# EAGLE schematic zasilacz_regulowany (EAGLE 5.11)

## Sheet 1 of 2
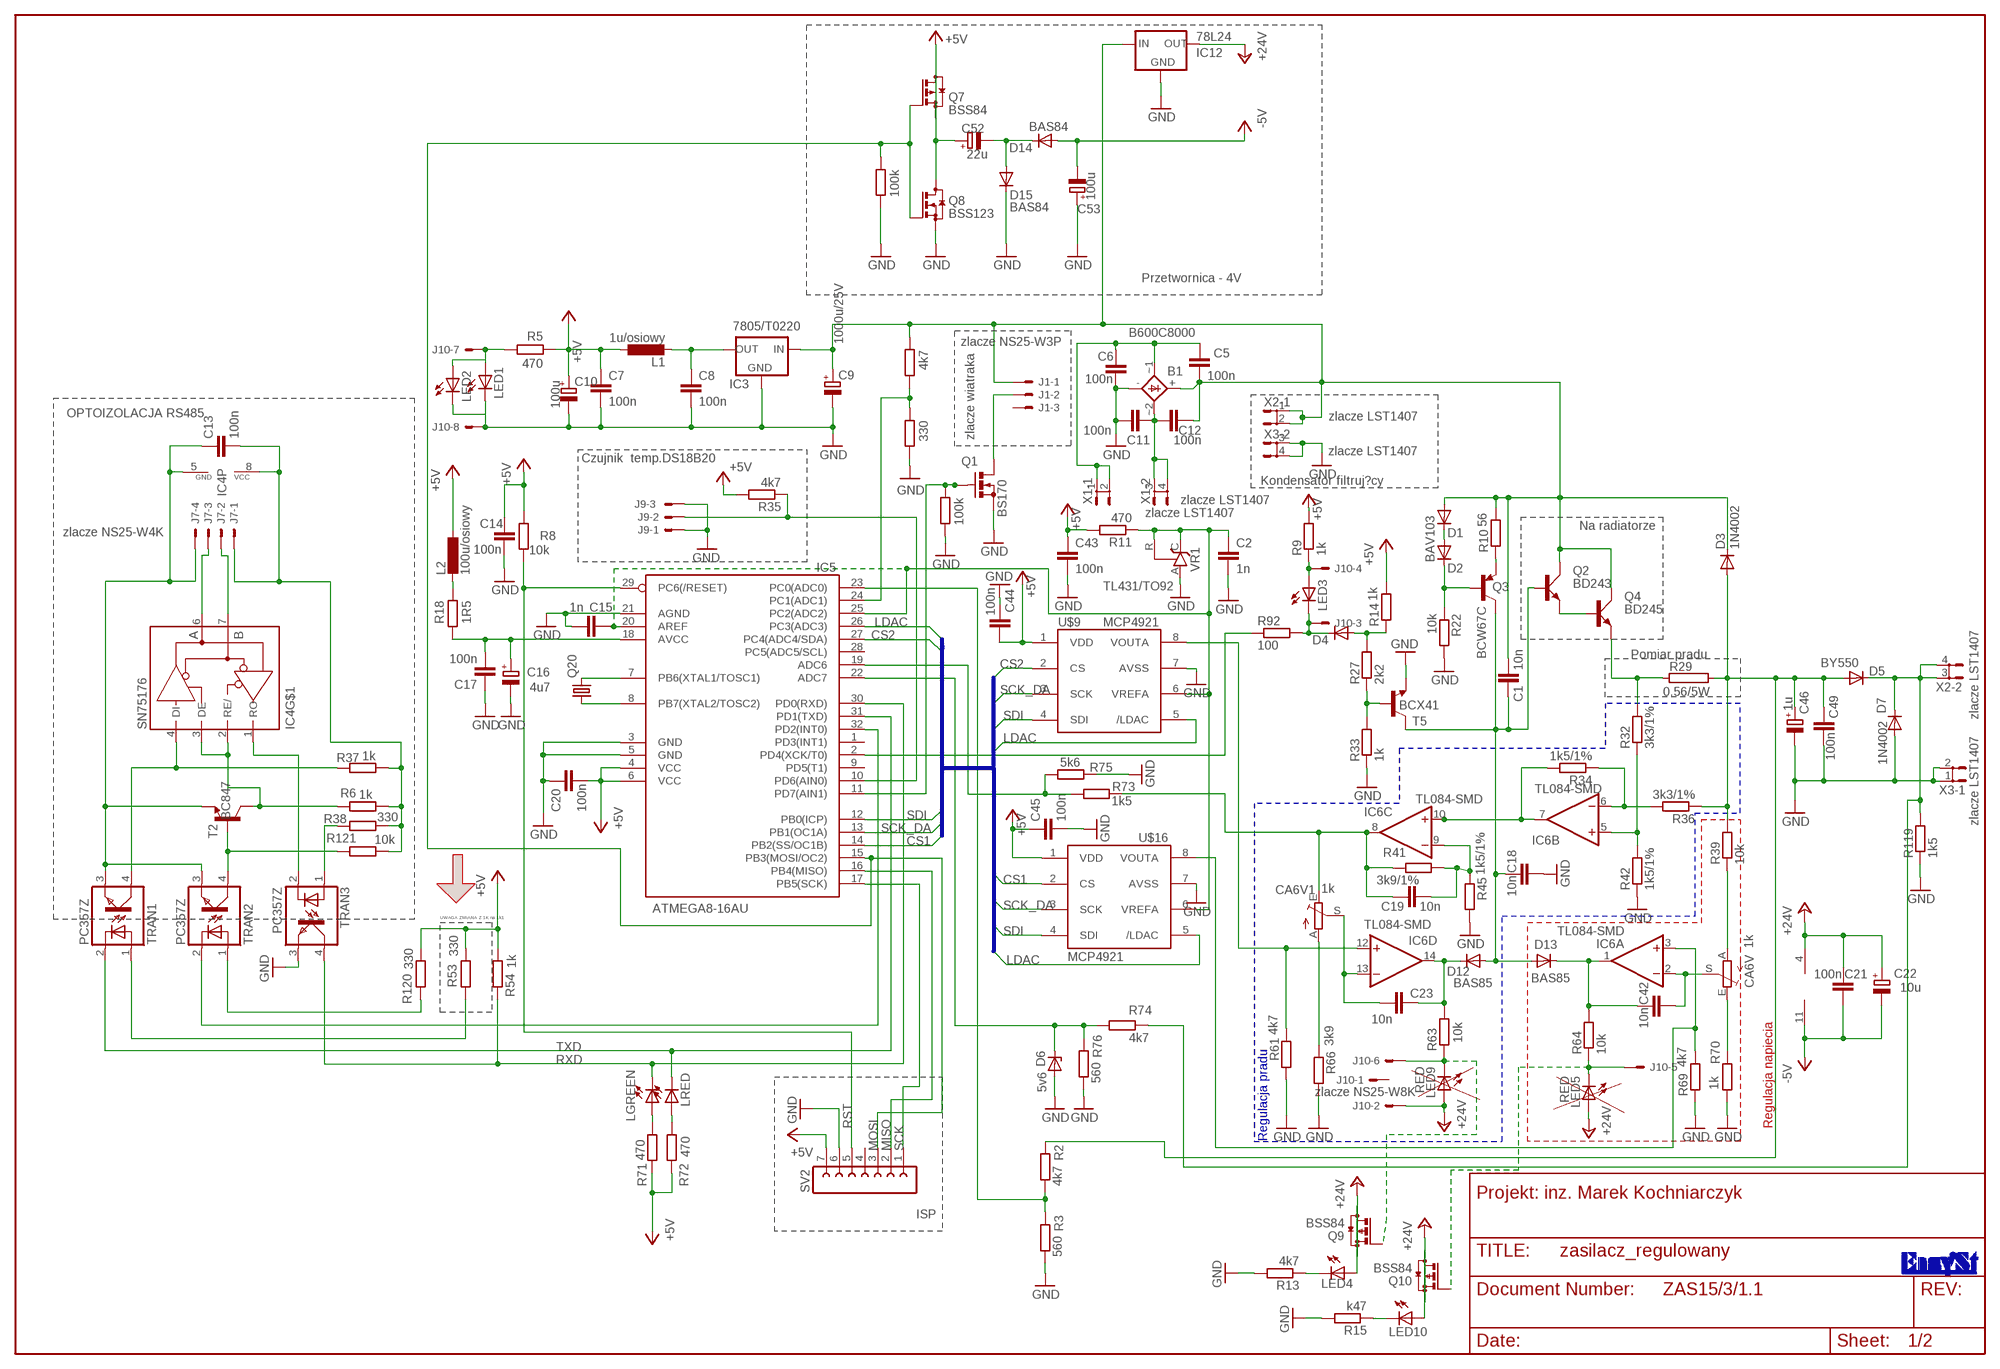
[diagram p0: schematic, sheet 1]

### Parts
B1  B600C8000  2KBB_R2  [2KBB_R2]
C1  10n  C-EUC0805  [C0805]
C2  1n  C-EUC0805  [C0805]
C5  100n  C-EUC0805  [C0805]
C6  100n  C-EUC0805  [C0805]
C7  100n  C-EUC0805  [C0805]
C8  100n  C-EUC0805  [C0805]
C9  1000u/25V  CPOL-EUTT5D11  [TT5D11]
C10  100u  CPOL-EUTT2D5  [TT2D5]
C11  100n  C-EUC0805  [C0805]
C12  100n  C-EUC0805  [C0805]
C13  100n  C-EUC0805  [C0805]
C14  100n  C-EUC0805  [C0805]
C15  1n  C-EUC0805  [C0805]
C16  4u7  CPOL-EUTT2D5  [TT2D5]
C17  100n  C-EUC0805  [C0805]
C18  10n  C-EUC0805  [C0805]
C19  10n  C-EUC0805  [C0805]
C20  100n  C-EUC0805  [C0805]
C21  100n  C-EUC0805  [C0805]
C22  10u  CPOL-EUTT2D5  [TT2D5]
C23  10n  C-EUC0805  [C0805]
C42  10n  C-EUC0805  [C0805]
C43  100n  C-EUC0805  [C0805]
C44  100n  C-EUC0805  [C0805]
C45  100n  C-EUC0805  [C0805]
C46  1u  CPOL-EUTT2D5  [TT2D5]
C49  100n  C-EUC0805  [C0805]
C52  22u  CPOL-EUTT2D5  [TT2D5]
C53  100u  CPOL-EUTT2D6  [TT2D6]
CA6V  1k  TRIM_EU-CA6H  [CA6H]
CA6V1  1k  TRIM_EU-CA6H  [CA6H]
D1  BAV103  DIODE-MINIMELF  [MINIMELF]
D2  BAV103  DIODE-MINIMELF  [MINIMELF]
D3  1N4002  DIODE-P1-10  [P1-10]
D4  DIODE-MINIMELF  [MINIMELF]
D5  BY550  DIODE-P6-15  [P6-15]
D6  5v6  ZENER-DIODESOT23  [SOT23]
D7  1N4002  DIODE-P1-10  [P1-10]
D12  BAS85  DIODE-MINIMELF  [MINIMELF]
D13  BAS85  DIODE-MINIMELF  [MINIMELF]
D14  BAS85  DIODE-MINIMELF  [MINIMELF]
D15  BAS85  DIODE-MINIMELF  [MINIMELF]
IC3  7805/T0220  78XXS  [78XXS]
IC4  SN75176  MAX481CSA  [SO08]
IC5  ATMEGA8-16AU  MEGA8-AI  [TQFP32-08]
IC6  TL084-SMD  TL084D  [SO14]
IC12  78L24  78LXX  [78LXX]
J1  zlacze NS25-W3P  22-27-2031-03  [6410-03]
J7  zlacze NS25-W4K  22-05-7048-04  [7395-04]
J9  zlacze NS25-W3P  22-27-2031-03  [6410-03]
J10  zlacze NS25-W8K  22-05-7088-08  [7395-08]
L1  1u/osiowy  L-EU0207/12  [0207/12]
L2  100u/osiowy  L-EU0207/10  [0207/10]
LED1  LED3MM  [LED3MM]
LED2  LED3MM  [LED3MM]
LED3  LED3MM  [LED3MM]
LED4  RED  LED3MM  [LED3MM]
LED5  RED  LED3MM  [LED3MM]
LED9  RED  LED3MM  [LED3MM]
LED10  RED  LED3MM  [LED3MM]
LGREEN  1206  LEDSMT1206  [1206]
LRED  1206  LEDSMT1206  [1206]
Q1  BS170  [SOT54E]
Q2  BD243  TIP41C  [TO220AV]
Q3  BCW67C  BCX71SMD  [SOT23]
Q4  BD245  TIP3055  [TOP3AV]
Q7  BSS84  [SOT23]
Q8  BSS123  [SOT23]
Q9  BSS84  [SOT23]
Q10  BSS84  [SOT23]
Q20  CRYSTALHC49S  [HC49/S]
R1  100k  R-EU_R0805  [R0805]
R2  4k7  R-EU_R0805  [R0805]
R3  560  R-EU_R0805  [R0805]
R4  4k7  R-EU_R0805  [R0805]
R5  470  R-EU_R0805  [R0805]
R6  1k  R-EU_R0805  [R0805]
R7  100k  R-EU_M0805  [M0805]
R8  10k  R-EU_R0805  [R0805]
R9  1k  R-EU_R0805  [R0805]
R10  56  R-EU_0207/10  [0207/10]
R11  470  R-EU_R0805  [R0805]
R12  330  R-EU_R0805  [R0805]
R13  4k7  R-EU_R0805  [R0805]
R14  1k  R-EU_R0805  [R0805]
R15  k47  R-EU_R0805  [R0805]
R18  1R5  R-EU_R0805  [R0805]
R22  10k  R-EU_R0805  [R0805]
R27  2k2  R-EU_R0805  [R0805]
R29  0.56/5W  RKH208-8  [KH208-8]
R32  3k3/1%  R-EU_R0805  [R0805]
R33  1k  R-EU_R0805  [R0805]
R34  1k5/1%  R-EU_R0805  [R0805]
R35  4k7  R-EU_R0805  [R0805]
R36  3k3/1%  R-EU_R0805  [R0805]
R37  1k  R-EU_R0805  [R0805]
R38  330  R-EU_M0805  [M0805]
R39  10k  R-EU_R0805  [R0805]
R41  3k9/1%  R-EU_R0805  [R0805]
R42  1k5/1%  R-EU_R0805  [R0805]
R45  1k5/1%  R-EU_R0805  [R0805]
R53  330  R-EU_R0805  [R0805]
R54  1k  R-EU_R0805  [R0805]
R61  4k7  R-EU_R0805  [R0805]
R63  10k  R-EU_R0805  [R0805]
R64  10k  R-EU_R0805  [R0805]
R66  3k9  R-EU_R0805  [R0805]
R69  4k7  R-EU_R0805  [R0805]
R70  1k  R-EU_R0805  [R0805]
R71  470  R-EU_R0805  [R0805]
R72  470  R-EU_R0805  [R0805]
R73  1k5  R-EU_R0805  [R0805]
R74  4k7  R-EU_R0805  [R0805]
R75  5k6  R-EU_R0805  [R0805]
R76  560  R-EU_R0805  [R0805]
R92  100  R-EU_R0805  [R0805]
R119  1k5  R-EU_0207/7  [0207/7]
R120  330  R-EU_R0805  [R0805]
R121  10k  R-EU_R0805  [R0805]
SV2  FE07-1  [FE07]
T2  BC847  BCX70SMD  [SOT23]
T5  BCX41  BCX70SMD  [SOT23]
TRAN1  PC357Z  [MFP4]
TRAN2  PC357Z  [MFP4]
TRAN3  PC357Z  [MFP4]
U$9  MCP4921  [SO-08]
U$16  MCP4921  [SO-08]
VR1  TL431/TO92  TL431CLP  [TO92-CLP]
X1  zlacze LST1407  SH5-2  [SH5-2]
X2  zlacze LST1407  SH5-2  [SH5-2]
X3  zlacze LST1407  SH5-2  [SH5-2]

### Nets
+5V: C7.1 C10.+ C14.1 C20.2 C43.1 C44.2 C45.1 IC5.4(VCC) IC5.6(VCC) L1.1 L2.1 Q7.2(S) R5.1 R8.2 R9.2 R11.2 R14.2 R35.2 R53.1 R54.1 R71.1 R72.1 R120.1 SV2.7 U$9.1(VDD) U$16.1(VDD) ; also sheet 2
+24V: C21.1 C22.+ IC6.4(P:V+) IC12.OUT J10.2 LED5.A LED9.A Q9.2(S) Q10.2(S)
-5V: C21.2 C22.- C53.- D14.A IC6.11(P:V-)
A: IC4.6(A) J7.3
ADC6: IC5.19(ADC6) R73.2 R75.2
ADC7: D6.3(C) IC5.22(ADC7) R74.1 R76.2
AVCC: C16.+ C17.2 IC5.18(AVCC) R18.2
B: IC4.7(B) J7.2
CS1: IC5.14(PB2(SS/OC1B)) U$16.2(CS)
CS2: IC5.27(PC4(ADC4/SDA)) U$9.2(CS)
GND: B1.- C2.2 C6.2 C7.2 C8.2 C9.- C10.- C11.1 C14.2 C15.1 C16.- C17.1 C18.2 C20.1 C43.2 C44.1 C45.2 C46.- C49.1 C53.+ D6.1(A) D7.A D15.C IC3.GND IC5.3(GND) IC5.5(GND) IC5.21(AGND) IC12.GND J9.1 J9.3 J10.8 LED1.K(C) LED2.K(C) Q1.S Q8.2(S) R1.2 R3.1 R7.2 R12.2 R13.2 R15.2 R22.2 R33.1 R42.1 R45.2 R61.1 R66.2 R69.1 R70.1 R75.1 R76.1 R119.1 SV2.6 T5.2(E) TRAN3.3(EMIT) U$9.7(AVSS) U$16.7(AVSS) VR1.A X3.1 X3.2 X3.3 X3.4
GND_RS485: C13.1 IC4.5(P:GND) J7.4 T2.2(E) TRAN1.3(EMIT) TRAN2.3(EMIT)
IOUT: IC6.12(D:+IN) R61.2 U$9.8(VOUTA)
LDAC: IC5.26(PC3(ADC3)) U$9.5(/LDAC) U$16.5(/LDAC)
MISO: IC5.16(PB4(MISO)) SV2.2
MOSI: IC5.15(PB3(MOSI/OC2)) Q7.1(G) Q8.1(G) R1.1 SV2.3
N$1: CA6V.A R39.1
N$2: IC6.6(B:-IN) R34.1 R36.2
N$3: C42.2 CA6V.S IC6.2(A:-IN)
N$4: IC6.5(B:+IN) R32.1 R42.2
N$5: IC6.7(B:OUT) IC6.10(C:+IN) R34.2
N$6: C23.1 CA6V1.S IC6.13(D:-IN)
N$7: C19.2 IC6.9(C:-IN) R41.2 R45.1
N$8: C19.1 CA6V1.E IC6.8(C:OUT) R41.1 R73.1
N$10: C1.1 C18.1 D12.A D13.A Q2.B Q3.3(C) T5.3(C)
N$11: R120.2 TRAN2.1(A)
N$12: IC5.32(PD2(INT0)) TRAN2.2(C)
N$14: CA6V.E R70.2
N$16: C23.2 D12.C IC6.14(D:OUT) R63.2
N$17: CA6V1.A R66.1
N$19: Q4.E R29.1 R32.2
N$22: D4.A R14.1 R27.2
N$23: D1.C D2.A
N$25: R27.1 R33.2 T5.1(B)
N$28: Q2.E Q4.B
N$31: LED4.A Q9.3(D)
N$33: C52.+ Q7.3(D) Q8.3(D)
N$34: IC4.4(DI) R37.2 TRAN1.4(COL)
N$35: IC5.10(PD6(AIN0)) J9.2 R35.1
N$36: D2.C Q3.1(B) R22.1
N$37: J10.6 LED9.K(C) Q9.1(G) R63.1
N$38: J10.5 LED5.K(C) Q10.1(G) R64.1
N$39: IC5.23(PC0(ADC0)) R2.1 R3.2
N$40: C46.+ C49.2 D3.A D5.A R2.2 R29.2 R36.1 R39.2
N$42: C52.- D14.C D15.A
N$43: L2.2 R18.1
N$44: R53.2 TRAN1.1(A)
N$45: IC4.1(RO) TRAN3.2(C)
N$47: IC5.7(PB6(XTAL1/TOSC1)) Q20.2
N$54: R38.2 TRAN3.1(A)
N$55: R121.2 T2.1(B) TRAN2.4(COL)
N$56: C8.1 IC3.OUT L1.2
N$57: J10.7 LED1.A LED2.A R5.2
N$59: D5.C D7.C R74.2 R119.2 X2.3 X2.4
N$60: C42.1 D13.C IC6.1(A:OUT) R64.2
N$64: LRED.A R72.2
N$65: IC4.2(RE/) IC4.3(DE) R6.2 T2.3(C)
N$66: LGREEN.A R71.2
N$67: Q3.2(E) R10.1
N$68: B1.~2(AC2) C11.2 C12.1 X1.3 X1.4
N$69: B1.~1(AC1) C5.1 C6.1 X1.1 X1.2
N$100: D4.C J10.3 LED3.K(C) R92.2
N$112: J1.2 Q1.D
N$115: IC5.11(PD7(AIN1)) Q1.G R7.1
N$124: LED4.K(C) R13.1
N$126: LED10.A Q10.3(D)
N$128: LED10.K(C) R15.1
N$130: IC5.8(PB7(XTAL2/TOSC2)) Q20.1
N$142: C2.1 C15.2 IC5.20(AREF) IC5.25(PC2(ADC2)) R11.1 U$9.6(VREFA) U$16.6(VREFA) VR1.C VR1.R
N$144: J10.4 LED3.A R9.1
RST: IC5.29(PC6(/RESET)) R8.1 SV2.5
RXD: IC5.30(PD0(RXD)) LGREEN.C R54.2 TRAN3.4(COL)
SCK: IC5.17(PB5(SCK)) SV2.1
SCK_DA: IC5.13(PB1(OC1A)) U$9.3(SCK) U$16.3(SCK)
SDI: IC5.12(PB0(ICP)) U$9.4(SDI) U$16.4(SDI)
TXD: IC5.31(PD1(TXD)) LRED.C TRAN1.2(C)
V+: B1.+ C1.2 C5.2 C9.+ C12.2 D1.A D3.C IC3.IN IC12.IN J1.1 Q2.C Q4.C R4.1 R10.2 X2.1 X2.2
V_WE: IC5.24(PC1(ADC1)) R4.2 R12.1
VCC_RS485: C13.2 IC4.8(P:VCC) J7.1 R6.1 R37.1 R38.1 R121.1
VOUT: IC6.3(A:+IN) R69.2 U$16.8(VOUTA)
ZAS_ON_OFF: IC5.2(PD4(XCK/T0)) R92.1
Unconnected: IC5.1(PD3(INT1)) IC5.9(PD5(T1)) IC5.28(PC5(ADC5/SCL)) J1.3 J10.1 SV2.4

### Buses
CS1,CS2,SCK_DA,SDI,LDAC

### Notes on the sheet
- BAS84
- BAS84
- Przetwornica - 4V
- OPTOIZOLACJA RS485
- zlacze wiatraka
- Czujnik  temp.DS18B20
- Kondensator filtruj?cy
- Na radiatorze
- BAV103
- Pomiar pradu
- ATMEGA8-16AU
- UWAGA ZMIANA Z 1K na 1k1
- Regulacja napiecia
- Regulacja pradu
- Projekt: inz. Marek Kochniarczyk
- ISP
- D:/logo_ensyst_1bit.bmp
- ZAS15/3/1.1

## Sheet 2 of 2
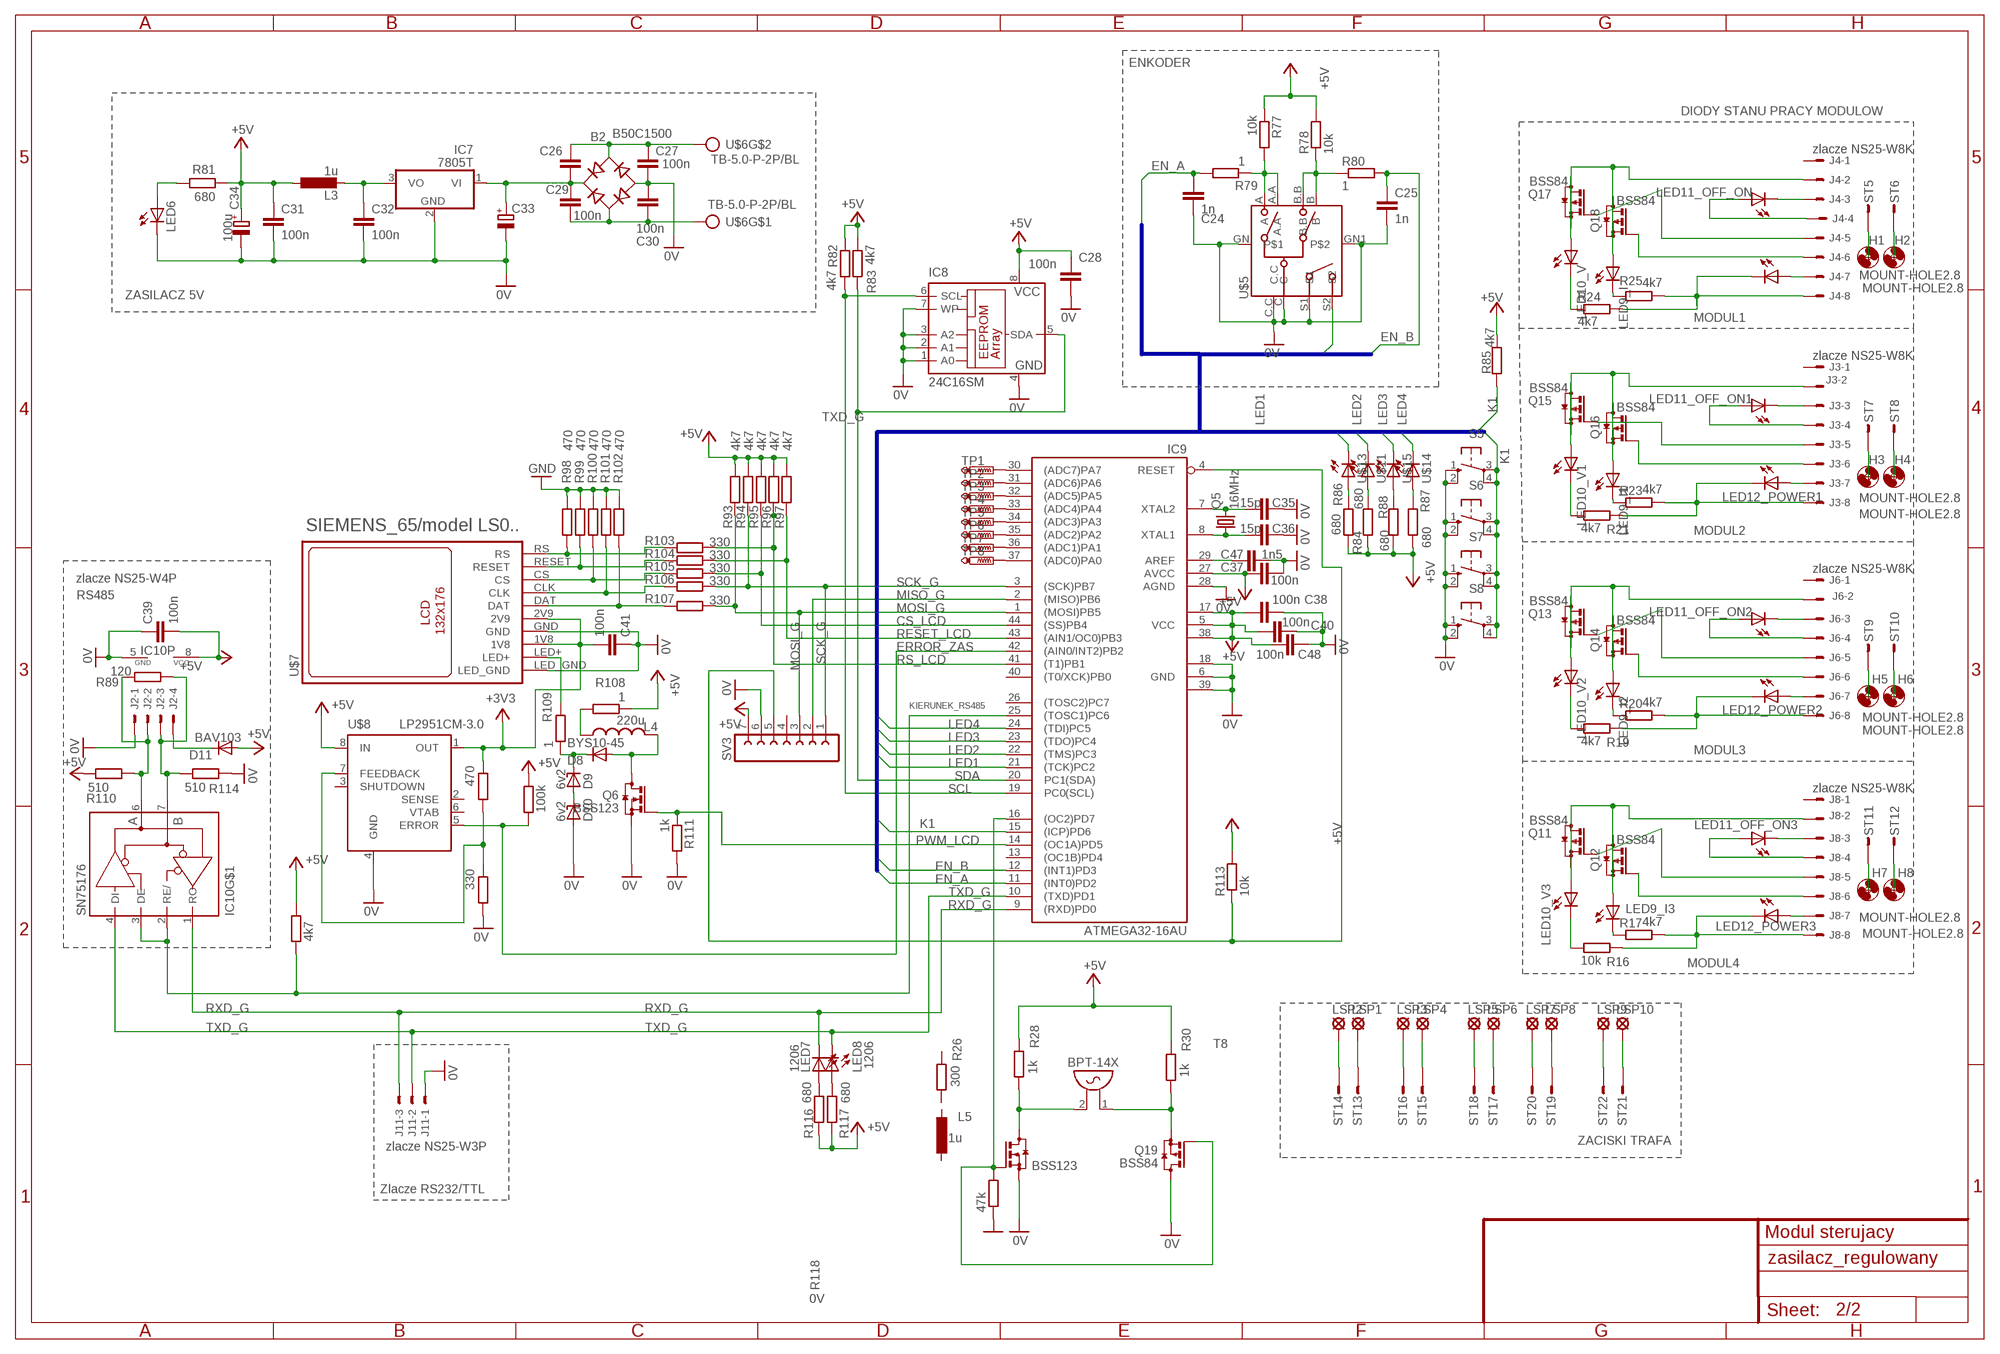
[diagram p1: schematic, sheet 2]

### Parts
B2  B50C1500  RB1A  [RB1A]
BPT-14X  BPT-14X  F/HGP  [F/HGP]
C24  1n  C-EUC0805  [C0805]
C25  1n  C-EUC0805  [C0805]
C26  100n  C-EUC1206  [C1206]
C27  100n  C-EUC1206  [C1206]
C28  100n  C-EUC0805  [C0805]
C29  100n  C-EUC1206  [C1206]
C30  100n  C-EUC1206  [C1206]
C31  100n  C-EUC0805  [C0805]
C32  100n  C-EUC0805  [C0805]
C33  1000u/25V  CPOL-EUTT5D11L  [TT5D11L]
C34  100u  CPOL-EUTT2D5L  [TT2D5L]
C35  15p  C-EUC0805K  [C0805K]
C36  15p  C-EUC0805K  [C0805K]
C37  100n  C-EUC0805K  [C0805K]
C38  100n  C-EUC0805K  [C0805K]
C39  100n  C-EUC0805  [C0805]
C40  100n  C-EUC0805K  [C0805K]
C41  100n  C-EUC0805K  [C0805K]
C47  1n5  C-EUC0805K  [C0805K]
C48  100n  C-EUC0805K  [C0805K]
D8  BYS10-45  BYS10  [SOD106A]
D9  6v2  BZX84CSMD  [TO236]
D10  6v2  BZX84CSMD  [TO236]
D11  BAV103  DIODE-MINIMELF  [MINIMELF]
H1  MOUNT-HOLE2.8  [2,8]
H2  MOUNT-HOLE2.8  [2,8]
H3  MOUNT-HOLE2.8  [2,8]
H4  MOUNT-HOLE2.8  [2,8]
H5  MOUNT-HOLE2.8  [2,8]
H6  MOUNT-HOLE2.8  [2,8]
H7  MOUNT-HOLE2.8  [2,8]
H8  MOUNT-HOLE2.8  [2,8]
IC7  7805T  [TO220H]
IC8  24C16SM  24C64SM  [SO-08M]
IC9  ATMEGA32-16AU  MEGA32-A  [TQFP44]
IC10  SN75176  MAX481CSA  [SO08]
J2  zlacze NS25-W4P  22-27-2041-04  [6410-04]
J3  zlacze NS25-W8K  22-27-2081-08  [6410-08]
J4  zlacze NS25-W8K  22-27-2081-08  [6410-08]
J6  zlacze NS25-W8K  22-27-2081-08  [6410-08]
J8  zlacze NS25-W8K  22-27-2081-08  [6410-08]
J11  zlacze NS25-W3P  22-27-2031-03  [6410-03]
L3  1u  L-EU0207/15  [0207/15@1]
L4  220u  L-US0207/12  [0207/12]
L5  1u  L-EU0207/15  [0207/15@1]
LED6  LED3mm  LED3MM  [LED3MM]
LED7  1206  LEDCHIPLED_1206  [CHIPLED_1206]
LED8  1206  LEDCHIPLED_1206  [CHIPLED_1206]
LED9_I  LED3MM  [LED3MM]
LED9_I1  LED3MM  [LED3MM]
LED9_I2  LED3MM  [LED3MM]
LED9_I3  LED3MM  [LED3MM]
LED10_V  LED3MM  [LED3MM]
LED10_V1  LED3MM  [LED3MM]
LED10_V2  LED3MM  [LED3MM]
LED10_V3  LED3MM  [LED3MM]
LED11_OFF_ON  LED3MM  [LED3MM]
LED11_OFF_ON1  LED3MM  [LED3MM]
LED11_OFF_ON2  LED3MM  [LED3MM]
LED11_OFF_ON3  LED3MM  [LED3MM]
LED12_POWER  LED3MM  [LED3MM]
LED12_POWER1  LED3MM  [LED3MM]
LED12_POWER2  LED3MM  [LED3MM]
LED12_POWER3  LED3MM  [LED3MM]
LSP1  SE14  [SE14]
LSP2  SE14  [SE14]
LSP3  SE14  [SE14]
LSP4  SE14  [SE14]
LSP5  SE14  [SE14]
LSP6  SE14  [SE14]
LSP7  SE14  [SE14]
LSP8  SE14  [SE14]
LSP9  SE14  [SE14]
LSP10  SE14  [SE14]
Q5  16MHz  CRYSTALHC49U70  [HC49U70]
Q6  BSS123  [SOT23]
Q11  BSS84  [SOT23]
Q12  BSS84  [SOT23]
Q13  BSS84  [SOT23]
Q14  BSS84  [SOT23]
Q15  BSS84  [SOT23]
Q16  BSS84  [SOT23]
Q17  BSS84  [SOT23]
Q18  BSS84  [SOT23]
Q19  BSS84  [SOT23]
R16  10k  R-EU_R0805  [R0805]
R17  4k7  R-EU_R0805  [R0805]
R19  4k7  R-EU_R0805  [R0805]
R20  4k7  R-EU_R0805  [R0805]
R21  4k7  R-EU_R0805  [R0805]
R23  4k7  R-EU_R0805  [R0805]
R24  4k7  R-EU_R0805  [R0805]
R25  4k7  R-EU_R0805  [R0805]
R26  300  R-EU_R0805  [R0805]
R28  1k  R-EU_R0805  [R0805]
R30  1k  R-EU_R0805  [R0805]
R77  10k  R-EU_M1206  [M1206]
R78  10k  R-EU_M1206  [M1206]
R79  1  R-EU_M1206  [M1206]
R80  1  R-EU_M1206  [M1206]
R81  680  R-EU_M0805  [M0805]
R82  4k7  R-EU_M0805  [M0805]
R83  4k7  R-EU_M0805  [M0805]
R84  680  R-EU_R0805  [R0805]
R85  4k7  R-EU_R0805  [R0805]
R86  680  R-EU_R0805  [R0805]
R87  680  R-EU_R0805  [R0805]
R88  680  R-EU_R0805  [R0805]
R89  120  R-EU_R0805  [R0805]
R90  470  R-EU_R0805  [R0805]
R91  330  R-EU_R0805  [R0805]
R93  4k7  R-EU_R0805  [R0805]
R94  4k7  R-EU_R0805  [R0805]
R95  4k7  R-EU_R0805  [R0805]
R96  4k7  R-EU_R0805  [R0805]
R97  4k7  R-EU_R0805  [R0805]
R98  470  R-EU_R0805  [R0805]
R99  470  R-EU_R0805  [R0805]
R100  470  R-EU_R0805  [R0805]
R101  470  R-EU_R0805  [R0805]
R102  470  R-EU_R0805  [R0805]
R103  330  R-EU_R0805  [R0805]
R104  330  R-EU_R0805  [R0805]
R105  330  R-EU_R0805  [R0805]
R106  330  R-EU_R0805  [R0805]
R107  330  R-EU_R0805  [R0805]
R108  1  R-EU_R0805  [R0805]
R109  1  R-EU_R0805  [R0805]
R110  510  R-EU_R0805  [R0805]
R111  1k  R-EU_R0805  [R0805]
R112  100k  R-EU_R0805  [R0805]
R113  10k  R-EU_M0805  [M0805]
R114  510  R-EU_R0805  [R0805]
R115  4k7  R-EU_M0805  [M0805]
R116  680  R-EU_M0805  [M0805]
R117  680  R-EU_M0805  [M0805]
R118  47k  R-EU_R0805  [R0805]
S5  10-XX  [B3F-10XX]
S6  10-XX  [B3F-10XX]
S7  10-XX  [B3F-10XX]
S8  10-XX  [B3F-10XX]
ST5  ST2,8  [ST2,8]
ST6  ST2,8  [ST2,8]
ST7  ST2,8  [ST2,8]
ST8  ST2,8  [ST2,8]
ST9  ST2,8  [ST2,8]
ST10  ST2,8  [ST2,8]
ST11  ST2,8  [ST2,8]
ST12  ST2,8  [ST2,8]
ST13  ST2,8  [ST2,8]
ST14  ST2,8  [ST2,8]
ST15  ST2,8  [ST2,8]
ST16  ST2,8  [ST2,8]
ST17  ST2,8  [ST2,8]
ST18  ST2,8  [ST2,8]
ST19  ST2,8  [ST2,8]
ST20  ST2,8  [ST2,8]
ST21  ST2,8  [ST2,8]
ST22  ST2,8  [ST2,8]
SV3  FE07-1  [FE07]
T8  BSS123  [SOT23]
TP1  PTR1B1,27  [B1,27]
TP2  PTR1B1,27  [B1,27]
TP3  PTR1B1,27  [B1,27]
TP4  PTR1B1,27  [B1,27]
TP5  PTR1B1,27  [B1,27]
TP6  PTR1B1,27  [B1,27]
TP7  PTR1B1,27  [B1,27]
TP8  PTR1B1,27  [B1,27]
U$5  ED16112O  [ENKODER_PROSTY]
U$6  TB-5.0-P-2P/BL  AK300/2_MK  [AK300/2_MK]
U$7  SIEMENS_65/model LS0..  SIEMENS_65  [SIEMENS65]
U$8  LP2951CM-3.0  LM2951  [SO08]
U$11  LED3MM  [LED3MM]
U$13  LED3MM  [LED3MM]
U$14  LED3MM  [LED3MM]
U$15  LED3MM  [LED3MM]

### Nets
0V: B2.- C24.2 C25.2 C27.2 C28.2 C30.1 C31.2 C32.2 C33.- C34.- C35.1 C36.1 C37.2 C38.1 C39.1 C40.1 C41.1 C47.2 C48.1 D10.A IC7.2(GND) IC8.1(A0) IC8.2(A1) IC8.3(A2) IC8.4(GND) IC8.7(WP) IC9.6(GND) IC9.18(GND1) IC9.28(AGND) IC9.39(GND2) IC10.5(P:GND) J2.1 J11.1 LED6.K(C) Q6.2(S) Q19.3(D) R91.1 R98.2 R99.2 R100.2 R101.2 R102.2 R111.2 R114.1 R118.1 S5.1(S) S5.2(S1) S6.1(S) S6.2(S1) S7.1(S) S7.2(S1) S8.1(S) S8.2(S1) SV3.6 T8.2(S) U$5.C U$5.C.C U$5.GN U$5.GN1 U$5.S1 U$7.GND U$7.LED_GND U$8.4(GND) ; supply symbol labelled GND
+3V3: C41.2 R90.2 U$7.1V8 U$7.2V9 U$8.1(OUT)
+5V: C28.1 C31.1 C34.+ C37.1 C38.2 C39.2 C40.2 C48.2 D11.A IC8.8(VCC) IC9.5(VCC) IC9.17(VCC1) IC9.27(AVCC) IC9.38(VCC2) IC10.8(P:VCC) L3.1 R28.2 R30.2 R77.1 R78.2 R81.1 R82.1 R83.1 R84.1 R85.1 R86.1 R87.1 R88.1 R93.2 R94.2 R95.2 R96.2 R97.2 R108.1 R110.2 R112.2 R113.2 R115.2 R116.1 R117.1 SV3.7 U$8.8(IN) ; also sheet 1
+_1: ST5.1(ST)
+_2: ST7.1(ST)
+_3: ST9.1(ST)
+_4: ST11.1(ST)
+_5: LSP1.MP ST13.1(ST)
+_6: LSP4.MP ST15.1(ST)
+_7: LSP6.MP ST17.1(ST)
+_8: LSP8.MP ST19.1(ST)
+_9: LSP10.MP ST21.1(ST)
-_1: ST6.1(ST)
-_2: ST8.1(ST)
-_3: ST10.1(ST)
-_4: ST12.1(ST)
-_5: LSP2.MP ST14.1(ST)
-_6: LSP3.MP ST16.1(ST)
-_7: LSP5.MP ST18.1(ST)
-_8: LSP7.MP ST20.1(ST)
-_9: LSP9.MP ST22.1(ST)
A_S: IC10.6(A) J2.2 R89.2 R110.1
B_S: IC10.7(B) J2.3 R89.1 R114.2
CS_LCD: IC9.44((SS)PB4) R95.1 R105.2
E_A: R77.2 R79.1 U$5.A U$5.A.A
E_B: R78.1 R80.1 U$5.B U$5.B.B
EN_A: C24.1 IC9.11((INT0)PD2) R79.2
EN_B: C25.1 IC9.12((INT1)PD3) R80.2
ERROR_ZAS: IC9.42((AIN0/INT2)PB2) R112.1 U$8.5(ERROR)
GND_M: J8.8 LED12_POWER3.K(C) R16.2 R17.2
GND_M1: J6.8 LED12_POWER2.K(C) R19.2 R20.2
GND_M2: J3.8 LED12_POWER1.K(C) R21.2 R23.2
GND_M3: J4.8 LED12_POWER.K(C) R24.2 R25.2
K1: IC9.15((ICP)PD6) R85.2 S5.3(P) S5.4(P1) S6.3(P) S6.4(P1) S7.3(P) S7.4(P1) S8.3(P) S8.4(P1) U$5.S2
KIERUNEK_RS485: IC9.25((TOSC1)PC6) IC10.2(RE/) IC10.3(DE) R115.1
LED1: IC9.21((TCK)PC2) U$13.K(C)
LED2: IC9.22((TMS)PC3) U$11.K(C)
LED3: IC9.23((TDO)PC4) U$15.K(C)
LED4: IC9.24((TDI)PC5) U$14.K(C)
MISO_G: IC9.2((MISO)PB6) SV3.2
MOSI_G: IC9.1((MOSI)PB5) R93.1 R107.2 SV3.3
N$9: LED10_V.K(C) R24.1
N$13: IC9.30((ADC7)PA7) TP1.PP(TP)
N$15: IC9.31((ADC6)PA6) TP2.PP(TP)
N$18: IC9.32((ADC5)PA5) TP3.PP(TP)
N$20: LED9_I.K(C) R25.1
N$21: D11.C J2.4
N$24: LED9_I.A Q18.3(D)
N$26: IC9.33((ADC4)PA4) TP4.PP(TP)
N$27: IC9.34((ADC3)PA3) TP5.PP(TP)
N$29: IC9.35((ADC2)PA2) TP6.PP(TP)
N$30: IC9.36((ADC1)PA1) TP7.PP(TP)
N$32: IC9.37((ADC0)PA0) TP8.PP(TP)
N$46: J4.7 LED12_POWER.A
N$53: J4.6 Q18.1(G)
N$58: C47.1 IC9.29(AREF)
N$63: BPT-14X.2 R28.1 T8.3(D)
N$70: J4.3 LED11_OFF_ON.K(C)
N$71: J4.4 LED11_OFF_ON.A
N$72: LED10_V1.A Q15.3(D)
N$73: LED10_V1.K(C) R21.1
N$74: LED9_I1.K(C) R23.1
N$75: J3.7 LED12_POWER1.A
N$76: LED9_I1.A Q16.3(D)
N$77: J3.3 LED11_OFF_ON1.K(C)
N$78: J3.4 LED11_OFF_ON1.A
N$79: R98.1 R103.1 U$7.RS
N$80: C35.2 IC9.7(XTAL2) Q5.2
N$81: LED10_V2.A Q13.3(D)
N$82: LED10_V2.K(C) R19.1
N$83: LED9_I2.K(C) R20.1
N$84: J6.7 LED12_POWER2.A
N$85: C36.2 IC9.8(XTAL1) Q5.1
N$86: LED7.A R116.2
N$87: LED8.A R117.2
N$89: R84.2 U$11.A
N$90: R100.1 R105.1 U$7.CS
N$91: R101.1 R106.1 U$7.CLK
N$92: R86.2 U$13.A
N$93: R109.2 U$7.LED+
N$94: R90.1 R91.2 U$8.7(FEEDBACK)
N$95: C32.1 IC7.3(VO) L3.2
N$96: LED6.A R81.2
N$97: B2.AC2 C29.2 C30.2 U$6.1
N$101: LED9_I2.A Q14.3(D)
N$103: J6.3 LED11_OFF_ON2.K(C)
N$104: R87.2 U$14.A
N$105: D8.A L4.2 Q6.3(D)
N$106: D9.A D10.C
N$107: D8.K D9.C R109.1
N$108: L4.1 R108.2
N$109: B2.AC1 C26.1 C27.1 U$6.2
N$110: B2.+ C26.2 C29.1 C33.+ IC7.1(VI)
N$111: R99.1 R104.1 U$7.RESET
N$113: R102.1 R107.1 U$7.DAT
N$114: J6.4 LED11_OFF_ON2.A
N$116: LED9_I3.K(C) R17.1
N$117: LED9_I3.A Q12.3(D)
N$118: J8.6 Q12.1(G)
N$119: J8.7 LED12_POWER3.A
N$120: R88.2 U$15.A
N$121: J8.5 Q11.1(G)
N$122: J8.3 LED11_OFF_ON3.K(C)
N$123: J8.4 LED11_OFF_ON3.A
N$125: BPT-14X.1 Q19.2(S) R30.1
N$129: J8.2 Q11.2(S) Q12.2(S)
N$131: LED10_V3.A Q11.3(D)
N$132: LED10_V3.K(C) R16.1
N$133: J6.6 Q14.1(G)
N$134: J6.5 Q13.1(G)
N$135: J6.2 Q13.2(S) Q14.2(S)
N$136: J3.6 Q16.1(G)
N$137: J3.5 Q15.1(G)
N$138: J3.2 Q15.2(S) Q16.2(S)
N$139: J4.5 Q17.1(G)
N$140: J4.2 Q17.2(S) Q18.2(S)
N$141: LED10_V.A Q17.3(D)
PIK: IC9.16((OC2)PD7) Q19.1(G) R118.2 T8.1(G)
PWM_LCD: IC9.14((OC1A)PD5) Q6.1(G) R111.1
RESET_LCD: IC9.43((AIN1/OC0)PB3) R97.1 R104.2
RS_LCD: IC9.41((T1)PB1) R96.1 R103.2
RST_G: IC9.4(RESET) R113.1 SV3.5
RXD_G: IC9.9((RXD)PD0) IC10.1(RO) J11.3 LED7.C
SCK_G: IC9.3((SCK)PB7) R94.1 R106.2 SV3.1
SCL: IC8.6(SCL) IC9.19(PC0(SCL)) R82.2
SDA: IC8.5(SDA) IC9.20(PC1(SDA)) R83.2
TXD_G: IC9.10((TXD)PD1) IC10.4(DI) J11.2 LED8.C
Unconnected: IC9.13((OC1B)PD4) IC9.26((TOSC2)PC7) IC9.40((T0/XCK)PB0) J3.1 J4.1 J6.1 J8.1 L5.1 L5.2 R26.1 R26.2 SV3.4 U$8.2(SENSE) U$8.6(VTAB)

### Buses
K1,K2,K3,K4,K5,K6,K7,K8,EN_A,EN_B,LED1,LED2,LED3,LED4

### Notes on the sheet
- ENKODER
- DIODY STANU PRACY MODULOW
- B50C1500
- ZASILACZ 5V
- MODUL1
- SIEMENS_65/model LS0.. | MODUL2
- RS485
- R89
- MODUL3
- R114
- R110
- MODUL4
- ZACISKI TRAFA
- Zlacze RS232/TTL
- Modul sterujacy

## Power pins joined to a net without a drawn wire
SHUTDOWN: U$8.3(SHUTDOWN)

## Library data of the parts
B1 = rectifier:2KBB_R2
B2 = rectifier:RB1A: RECTIFIER 1 A
BPT-14X = buzzer:F/HGP: BUZZER
C1 C2 C5-C8 C11-C15 C17-C21 C23-C32 C35-C45 C47-C49 = rcl:C-EU: CAPACITOR, European symbol
C9 C10 C16 C22 C33 C34 C46 C52 C53 = rcl:CPOL-EU: POLARIZED CAPACITOR, European symbol
CA6V CA6V1 = pot:TRIM_EU-: POTENTIOMETER
D1-D5 D7 D11-D15 = diode:DIODE-: DIODE
D6 = diode:ZENER-DIODE: Z-Diode
D8 = telefunken:BYS10: DIODE
D9 D10 = diode:BZX84CSMD: Z DIODE
H1-H8 = holes:MOUNT-HOLE: MOUNTING HOLE with drill center marker
IC3 = v-reg:78XXS: VOLTAGE REGULATOR
IC4 IC10 = maxim:MAX481CSA: RS485 TRANSEIVER
IC5 = atmel:MEGA8: MICROCONTROLLER 8 Kbytes FLASH 1 kbytes SRAM 512 bytes EEPROM USART 6-channel 10 bit ADC 2-channel 8 bit ADC Source: avr.lbr
IC6 = linear:TL084: OP AMP
IC7 = linear:78*: Positive VOLTAGE REGULATOR Source: http://cache.national.com/ds/LM/LM78L05.pdf http://www.fairchildsemi.com/ds/LM/LM7805.pdf
IC8 = microchip:24*: Serial EEPROM I2C
IC9 = atmel:MEGA32: MICROCONTROLLER 32 Kbytes FLASH 2 Kbytes SRAM 1 Kbytes EEPROM USART 8-channel 10 bit ADC Source: www.atmel.com .. doc2503.pdf
IC12 = v-reg:78LXX: VOLTAGE REGULATOR
J1 J9 J11 = con-molex:22-?-03: CONNECTOR wire to board 2.54 mm (.1 inch) pitch header
J2 J7 = con-molex:22-?-04: CONNECTOR wire to board 2.54 mm (.1 inch) pitch header
J3 J4 J6 J8 J10 = con-molex:22-?-08: CONNECTOR wire to board 2.54 mm (.1 inch) pitch header
L1-L3 L5 = rcl:L-EU: INDUCTOR, European symbol
L4 = rcl:L-US: INDUCTOR, American symbol
LED1-LED9 LED9_I LED9_I1-LED9_I3 LED10 LED10_V LED10_V1-LED10_V3 LED11_OFF_ON LED11_OFF_ON1-LED11_OFF_ON3 LED12_POWER LED12_POWER1-LED12_POWER3 LGREEN LRED U$11 U$13-U$15 = led:LED: LED
LSP1-LSP10 = solpad:SE14: SOLDER PAD
Q1 = transistor-small-signal:BS170: N-CHANNEL MOS FET
Q2 = transistor-power:TIP41C: NPN TRANSISTOR
Q3 = transistor-pnp:BCX71SMD: PNP Transistor
Q4 = transistor-power:TIP3055: NPN TRANSISTOR
Q5 = crystal:CRYSTAL: CRYSTAL; OC_FARNELL: unknown; OC_NEWARK: unknown
Q6 Q8 T8 = transistor-small-signal:BSS123: N-CHANNEL MOS FET
Q7 Q9-Q19 = transistor-small-signal:BSS84: P-CHANNEL MOS FET
Q20 = crystal:CRYSTAL: CRYSTAL; OC_FARNELL: 1667008; OC_NEWARK: unknown
R1-R28 R30 R32-R39 R41 R42 R45 R53 R54 R61 R63 R64 R66 R69-R121 = rcl:R-EU_: RESISTOR, European symbol
R29 = resistor-power:R: Power Resitor
S5-S8 = switch-omron:10-XX: OMRON SWITCH
ST5-ST22 = con-rib:ST2,8: RIBBON CABLE CONNECTOR
SV2 SV3 = con-lsta:FE07-1: FEMALE HEADER
T2 T5 = transistor:BCX70SMD: NPN TRANSISTOR
TP1-TP8 = testpad:PTR1: TEST PIN
TRAN1-TRAN3 = optocoupler:PC357Z
U$5 = piher:ED16112O
U$6 = con-ptr500:AK300/2_MK
U$7 = display-lcd:SIEMENS_65
U$8 = linear:LM2951
U$9 U$16 = microchip:MCP4921
VR1 = v-reg:TL431CLP: VOLTAGE REGULATOR
X1-X3 = con-rib:SH5-2: RIBBON CABLE CONNECTOR Flachstecker / Faston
